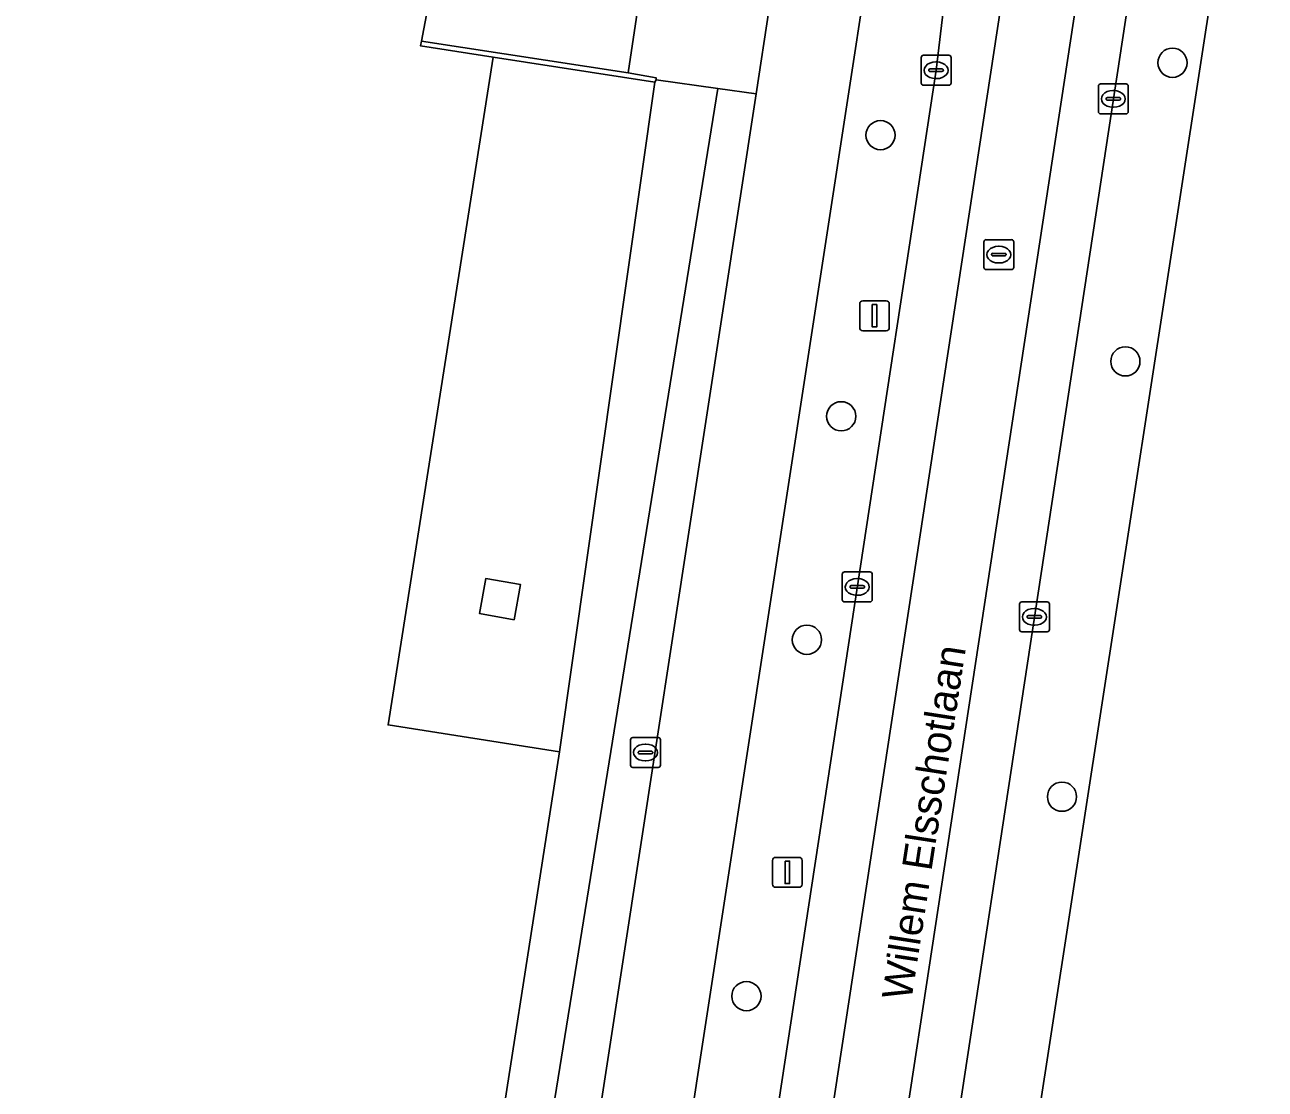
# Model space of a CAD drawing. Extents: x 161090 to 161692, y 379509 to 380907.
# Drawn here: x 161334.14 to 161375.66, y 380617.09 to 380652.7 of the extents above; entities that cross this region are included whole.
import ezdxf

# ---------------------------------------------------------------- set-up
doc = ezdxf.new("R2010")
doc.units = 0
for name, color, linetype in [('IMGEO_Boom', 7, 'Continuous'), ('IMGEO_Brandkraan', 7, 'Continuous'), ('IMGEO_Fietspad_gesloten', 7, 'Continuous'), ('IMGEO_Groenvoorziening', 7, 'Continuous'), ('IMGEO_Haag', 7, 'Continuous'), ('IMGEO_Hek', 7, 'Continuous'), ('IMGEO_Kolk', 7, 'Continuous'), ('IMGEO_Lichtmast', 7, 'Continuous'), ('IMGEO_Muur', 7, 'Continuous'), ('IMGEO_Openbare_ruimte_label', 7, 'Continuous'), ('IMGEO_Pand', 7, 'Continuous'), ('IMGEO_Rijbaan_lokaal_gesloten', 7, 'Continuous'), ('IMGEO_Rijbaan_lokaal_open', 7, 'Continuous'), ('IMGEO_Rioolput', 7, 'Continuous'), ('IMGEO_Terreindeel_gesloten', 7, 'Continuous'), ('IMGEO_Voetpad_open', 7, 'Continuous')]:
    doc.layers.add(name, color=color, linetype=linetype)

msp = doc.modelspace()

# ---------------------------------------------------------------- linework, layer by layer
at = {"layer": 'IMGEO_Boom'}
for centre in [(161372.554, 380651.434), (161362.782, 380649.011), (161370.978, 380641.442), (161361.467, 380639.604), (161360.319, 380632.127), (161368.856, 380626.877), (161358.295, 380620.204)]:
    msp.add_circle(centre, 0.489, dxfattribs=at)
at = {"layer": 'IMGEO_Brandkraan'}
for p, q in [((161354.415, 380627.93), (161354.415, 380628.782)), ((161354.49, 380628.856), (161355.342, 380628.856)), ((161355.416, 380628.782), (161355.416, 380627.93)), ((161354.674, 380628.35), (161354.674, 380628.362)), ((161355.112, 380628.313), (161354.714, 380628.313)), ((161354.717, 380628.399), (161355.115, 380628.399)), ((161354.903, 380628.636), (161354.928, 380628.636)), ((161355.158, 380628.362), (161355.158, 380628.35)), ((161355.342, 380627.856), (161354.49, 380627.856)), ((161354.926, 380628.076), (161354.901, 380628.076))]:
    msp.add_line(p, q, dxfattribs=at)
for points in [[(161354.415, 380627.93), (161354.415, 380628.782)], [(161354.49, 380628.856), (161355.342, 380628.856)], [(161355.416, 380628.782), (161355.416, 380627.93)], [(161355.342, 380627.856), (161354.49, 380627.856)]]:
    msp.add_lwpolyline(points, dxfattribs=at)
for centre, radius, start, end in [((161354.492, 380628.78), 0.0765, 91.552, 178.448), ((161354.492, 380628.78), 0.0765, 91.552, 178.448), ((161355.34, 380628.78), 0.0765, 1.552, 88.448), ((161355.34, 380628.78), 0.0765, 1.552, 88.448), ((161354.714, 380628.359), 0.0403, 85.8775, 175.7526), ((161354.711, 380628.349), 0.0366, 178.938, 274.7102), ((161355.115, 380628.356), 0.043, 264.8664, 352.4533), ((161355.119, 380628.361), 0.0386, 1.7309, 96.639), ((161354.492, 380627.932), 0.0765, 181.552, 268.448), ((161354.492, 380627.932), 0.0765, 181.552, 268.448), ((161355.34, 380627.932), 0.0765, 271.552, 358.448), ((161355.34, 380627.932), 0.0765, 271.552, 358.448)]:
    msp.add_arc(centre, radius, start, end, dxfattribs=at)
for centre, major_axis, ratio, start_param, end_param in [((161354.902, 380628.356), (-0.387, 0.002), 0.722429, 4.712389, 7.853982), ((161354.927, 380628.356), (-0.39, 0.002), 0.717154, 1.570796, 4.712389)]:
    msp.add_ellipse(centre, major_axis=major_axis, ratio=ratio, start_param=start_param, end_param=end_param, dxfattribs=at)
at = {"layer": 'IMGEO_Fietspad_gesloten'}
for points in [[(161365.033, 380672.035), (161366.062, 380679.022), (161370.741, 380709.1), (161371.715, 380716.23), (161380.846, 380774.64), (161377.763, 380775.191), (161374.457, 380753.641), (161374.222, 380752.111), (161368.715, 380716.224), (161367.825, 380710.422), (161362.964, 380678.743), (161362.07, 380672.915), (161359.052, 380653.248), (161358.615, 380650.395), (161352.499, 380610.536), (161352.063, 380607.696), (161344.427, 380557.933), (161343.697, 380553.172), (161343.539, 380552.144), (161341.187, 380536.812), (161341.053, 380535.941), (161340.209, 380530.441), (161339.339, 380524.771), (161336.97, 380509.331)], [(161335.342, 380478.178), (161335.568, 380479.642), (161342.437, 380524.075), (161343.313, 380530.047), (161346.723, 380552.271), (161347.54, 380558.203), (161365.033, 380672.035)]]:
    msp.add_lwpolyline(points, dxfattribs=at)
at = {"layer": 'IMGEO_Groenvoorziening'}
for points in [[(161405.29, 380858.44), (161406.537, 380866.558), (161406.318, 380866.529), (161406.225, 380866.182), (161404.5, 380859.729), (161400.962, 380846.207), (161400.622, 380844.851), (161395.87, 380814.342), (161392.957, 380796.042), (161379.164, 380706.261), (161373.065, 380666.559), (161354.682, 380545.949), (161344.875, 380482.113), (161345.249, 380482.081)], [(161347.003, 380477.776), (161347.606, 380481.216), (161353.592, 380520.726), (161366.925, 380608.735), (161376.121, 380668.459), (161405.29, 380858.44)], [(161483.889, 380845.433), (161405.29, 380858.44), (161376.121, 380668.459), (161366.925, 380608.735), (161353.592, 380520.726), (161347.606, 380481.216)], [(161365.033, 380672.035), (161347.54, 380558.203)], [(161351.073, 380562.281), (161364.643, 380651.182), (161364.91, 380653.432), (161367.178, 380667.879)]]:
    msp.add_lwpolyline(points, dxfattribs=at)
for points in [[(161355.234, 380650.781), (161349.821, 380651.619), (161346.301, 380629.278), (161352.038, 380628.383)], [(161357.34, 380650.575), (161355.268, 380650.867), (161355.234, 380650.781), (161352.038, 380628.383), (161349.332, 380611.003), (161350.91, 380610.77)], [(161358.615, 380650.395), (161357.34, 380650.575), (161350.91, 380610.77), (161352.499, 380610.536)], [(161350.731, 380633.977), (161350.52, 380632.797), (161349.358, 380633.011), (161349.569, 380634.173)]]:
    msp.add_lwpolyline(points, close=True, dxfattribs=at)
at = {"layer": 'IMGEO_Haag'}
msp.add_lwpolyline([(161357.34, 380650.575), (161355.268, 380650.867), (161355.234, 380650.781), (161352.038, 380628.383), (161349.332, 380611.003), (161350.91, 380610.77)], close=True, dxfattribs=at)
at = {"layer": 'IMGEO_Hek'}
msp.add_lwpolyline([(161353.592, 380520.726), (161366.925, 380608.735), (161376.121, 380668.459)], dxfattribs=at)
at = {"layer": 'IMGEO_Kolk'}
for p, q in [((161364.142, 380650.756), (161364.142, 380651.608)), ((161364.217, 380651.682), (161365.069, 380651.682)), ((161365.143, 380651.608), (161365.143, 380650.756)), ((161364.401, 380651.176), (161364.401, 380651.188)), ((161364.839, 380651.139), (161364.441, 380651.139)), ((161364.444, 380651.225), (161364.842, 380651.225)), ((161364.63, 380651.462), (161364.655, 380651.462)), ((161364.885, 380651.188), (161364.885, 380651.176)), ((161365.069, 380650.682), (161364.217, 380650.682)), ((161364.653, 380650.902), (161364.628, 380650.902)), ((161370.149, 380650.724), (161371.001, 380650.724)), ((161370.074, 380649.798), (161370.074, 380650.65)), ((161370.376, 380650.267), (161370.774, 380650.267)), ((161370.562, 380650.504), (161370.587, 380650.504)), ((161371.075, 380650.65), (161371.075, 380649.798)), ((161370.333, 380650.218), (161370.333, 380650.23)), ((161370.771, 380650.181), (161370.373, 380650.181)), ((161370.585, 380649.944), (161370.56, 380649.944)), ((161370.817, 380650.23), (161370.817, 380650.218)), ((161371.001, 380649.724), (161370.149, 380649.724)), ((161361.503, 380633.469), (161361.503, 380634.321)), ((161361.578, 380634.395), (161362.43, 380634.395)), ((161361.991, 380634.175), (161362.016, 380634.175)), ((161362.504, 380634.321), (161362.504, 380633.469)), ((161361.762, 380633.889), (161361.762, 380633.901)), ((161362.2, 380633.852), (161361.802, 380633.852)), ((161361.805, 380633.938), (161362.203, 380633.938)), ((161362.246, 380633.901), (161362.246, 380633.889)), ((161362.43, 380633.395), (161361.578, 380633.395)), ((161362.014, 380633.615), (161361.989, 380633.615)), ((161367.433, 380632.467), (161367.433, 380633.319)), ((161367.508, 380633.393), (161368.36, 380633.393)), ((161368.434, 380633.319), (161368.434, 380632.467)), ((161367.692, 380632.887), (161367.692, 380632.899)), ((161368.13, 380632.85), (161367.732, 380632.85)), ((161367.735, 380632.936), (161368.133, 380632.936)), ((161367.921, 380633.173), (161367.946, 380633.173)), ((161368.176, 380632.899), (161368.176, 380632.887)), ((161367.944, 380632.613), (161367.919, 380632.613)), ((161368.36, 380632.393), (161367.508, 380632.393))]:
    msp.add_line(p, q, dxfattribs=at)
for points in [[(161364.142, 380650.756), (161364.142, 380651.608)], [(161364.217, 380651.682), (161365.069, 380651.682)], [(161365.143, 380651.608), (161365.143, 380650.756)], [(161365.069, 380650.682), (161364.217, 380650.682)], [(161370.149, 380650.724), (161371.001, 380650.724)], [(161370.074, 380649.798), (161370.074, 380650.65)], [(161371.075, 380650.65), (161371.075, 380649.798)], [(161371.001, 380649.724), (161370.149, 380649.724)], [(161361.503, 380633.469), (161361.503, 380634.321)], [(161361.578, 380634.395), (161362.43, 380634.395)], [(161362.504, 380634.321), (161362.504, 380633.469)], [(161362.43, 380633.395), (161361.578, 380633.395)], [(161367.433, 380632.467), (161367.433, 380633.319)], [(161367.508, 380633.393), (161368.36, 380633.393)], [(161368.434, 380633.319), (161368.434, 380632.467)], [(161368.36, 380632.393), (161367.508, 380632.393)]]:
    msp.add_lwpolyline(points, dxfattribs=at)
for centre, radius, start, end in [((161364.219, 380651.606), 0.0765, 91.552, 178.448), ((161364.219, 380651.606), 0.0765, 91.552, 178.448), ((161365.067, 380651.606), 0.0765, 1.552, 88.448), ((161365.067, 380651.606), 0.0765, 1.552, 88.448), ((161364.441, 380651.185), 0.0403, 85.8775, 175.7526), ((161364.438, 380651.175), 0.0366, 178.938, 274.7102), ((161364.842, 380651.182), 0.043, 264.8664, 352.4533), ((161364.846, 380651.187), 0.0386, 1.7309, 96.639), ((161364.219, 380650.758), 0.0765, 181.552, 268.448), ((161364.219, 380650.758), 0.0765, 181.552, 268.448), ((161365.067, 380650.758), 0.0765, 271.552, 358.448), ((161365.067, 380650.758), 0.0765, 271.552, 358.448), ((161370.151, 380650.648), 0.0765, 91.552, 178.448), ((161370.151, 380650.648), 0.0765, 91.552, 178.448), ((161370.999, 380650.648), 0.0765, 1.552, 88.448), ((161370.999, 380650.648), 0.0765, 1.552, 88.448), ((161370.373, 380650.227), 0.0403, 85.8775, 175.7526), ((161370.778, 380650.229), 0.0386, 1.7309, 96.639), ((161370.37, 380650.217), 0.0366, 178.938, 274.7102), ((161370.774, 380650.224), 0.043, 264.8664, 352.4533), ((161370.151, 380649.8), 0.0765, 181.552, 268.448), ((161370.151, 380649.8), 0.0765, 181.552, 268.448), ((161370.999, 380649.8), 0.0765, 271.552, 358.448), ((161370.999, 380649.8), 0.0765, 271.552, 358.448), ((161361.58, 380634.319), 0.0765, 91.552, 178.448), ((161361.58, 380634.319), 0.0765, 91.552, 178.448), ((161362.428, 380634.319), 0.0765, 1.552, 88.448), ((161362.428, 380634.319), 0.0765, 1.552, 88.448), ((161361.802, 380633.898), 0.0403, 85.8775, 175.7526), ((161361.799, 380633.888), 0.0366, 178.938, 274.7102), ((161362.203, 380633.895), 0.043, 264.8664, 352.4533), ((161362.207, 380633.9), 0.0386, 1.7309, 96.639), ((161361.58, 380633.471), 0.0765, 181.552, 268.448), ((161361.58, 380633.471), 0.0765, 181.552, 268.448), ((161362.428, 380633.471), 0.0765, 271.552, 358.448), ((161362.428, 380633.471), 0.0765, 271.552, 358.448), ((161367.51, 380633.317), 0.0765, 91.552, 178.448), ((161367.51, 380633.317), 0.0765, 91.552, 178.448), ((161368.358, 380633.317), 0.0765, 1.552, 88.448), ((161368.358, 380633.317), 0.0765, 1.552, 88.448), ((161367.732, 380632.896), 0.0403, 85.8775, 175.7526), ((161367.729, 380632.886), 0.0366, 178.938, 274.7102), ((161368.133, 380632.893), 0.043, 264.8664, 352.4533), ((161368.137, 380632.898), 0.0386, 1.7309, 96.639), ((161367.51, 380632.469), 0.0765, 181.552, 268.448), ((161367.51, 380632.469), 0.0765, 181.552, 268.448), ((161368.358, 380632.469), 0.0765, 271.552, 358.448), ((161368.358, 380632.469), 0.0765, 271.552, 358.448)]:
    msp.add_arc(centre, radius, start, end, dxfattribs=at)
for centre, major_axis, ratio, start_param, end_param in [((161364.629, 380651.182), (-0.387, 0.002), 0.722429, 4.712389, 7.853982), ((161364.654, 380651.182), (-0.39, 0.002), 0.717154, 1.570796, 4.712389), ((161370.561, 380650.224), (-0.387, 0.002), 0.722429, 4.712389, 7.853982), ((161370.586, 380650.224), (-0.39, 0.002), 0.717154, 1.570796, 4.712389), ((161361.99, 380633.895), (-0.387, 0.002), 0.722429, 4.712389, 7.853982), ((161362.015, 380633.895), (-0.39, 0.002), 0.717154, 1.570796, 4.712389), ((161367.92, 380632.893), (-0.387, 0.002), 0.722429, 4.712389, 7.853982), ((161367.945, 380632.893), (-0.39, 0.002), 0.717154, 1.570796, 4.712389)]:
    msp.add_ellipse(centre, major_axis=major_axis, ratio=ratio, start_param=start_param, end_param=end_param, dxfattribs=at)
at = {"layer": 'IMGEO_Lichtmast'}
for p, q in [((161362.086, 380642.569), (161362.086, 380643.369)), ((161362.086, 380643.369), (161362.086, 380642.569)), ((161362.186, 380643.469), (161362.976, 380643.469)), ((161362.976, 380643.469), (161362.186, 380643.469)), ((161363.076, 380643.369), (161363.076, 380642.569)), ((161363.076, 380642.569), (161363.076, 380643.369)), ((161362.976, 380642.469), (161362.186, 380642.469)), ((161362.186, 380642.469), (161362.976, 380642.469)), ((161359.17, 380623.945), (161359.17, 380624.745)), ((161359.17, 380624.745), (161359.17, 380623.945)), ((161359.27, 380624.845), (161360.06, 380624.845)), ((161360.06, 380624.845), (161359.27, 380624.845)), ((161360.16, 380624.745), (161360.16, 380623.945)), ((161360.16, 380623.945), (161360.16, 380624.745)), ((161360.06, 380623.845), (161359.27, 380623.845)), ((161359.27, 380623.845), (161360.06, 380623.845))]:
    msp.add_line(p, q, dxfattribs=at)
for points in [[(161362.506, 380643.344), (161362.656, 380643.344), (161362.656, 380642.594), (161362.506, 380642.594), (161362.506, 380643.344)], [(161359.59, 380624.72), (161359.74, 380624.72), (161359.74, 380623.97), (161359.59, 380623.97), (161359.59, 380624.72)]]:
    msp.add_lwpolyline(points, dxfattribs=at)
for centre, start, end in [((161362.186, 380643.369), 90, 180), ((161362.186, 380643.369), 90, 180), ((161362.976, 380643.369), 0, 90), ((161362.976, 380643.369), 360, 90), ((161362.186, 380642.569), 180, 270), ((161362.186, 380642.569), 180, 270), ((161362.976, 380642.569), 270, 0), ((161362.976, 380642.569), 270, 0), ((161359.27, 380624.745), 90, 180), ((161359.27, 380624.745), 90, 180), ((161360.06, 380624.745), 0, 90), ((161360.06, 380624.745), 360, 90), ((161359.27, 380623.945), 180, 270), ((161359.27, 380623.945), 180, 270), ((161360.06, 380623.945), 270, 0), ((161360.06, 380623.945), 270, 0)]:
    msp.add_arc(centre, 0.1, start, end, dxfattribs=at)
at = {"layer": 'IMGEO_Muur'}
msp.add_lwpolyline([(161355.234, 380650.781), (161355.268, 380650.867), (161355.271, 380650.933), (161354.34, 380651.099), (161347.42, 380652.158), (161347.389, 380651.995), (161349.821, 380651.619)], close=True, dxfattribs=at)
at = {"layer": 'IMGEO_Pand'}
msp.add_lwpolyline([(161349.332, 380611.003), (161352.038, 380628.383), (161346.301, 380629.278), (161349.821, 380651.619), (161347.389, 380651.995), (161347.42, 380652.158), (161347.94, 380654.933), (161347.981, 380655.15), (161350.309, 380654.767), (161351.908, 380665.091), (161349.549, 380665.469), (161350.974, 380674.355), (161351.021, 380674.65), (161350.918, 380674.666), (161328.544, 380678.189), (161323.902, 380678.927), (161318.782, 380679.713), (161325.548, 380722.987)], dxfattribs=at)
at = {"layer": 'IMGEO_Rijbaan_lokaal_gesloten'}
for points in [[(161375.194, 380708.235), (161388.922, 380797.51), (161396.234, 380843.996), (161396.663, 380846.991), (161394.901, 380847.24), (161394.664, 380845.21), (161392.523, 380831.905), (161390.03, 380815.808), (161385.145, 380784.362), (161382.973, 380770.386), (161375.271, 380720.147), (161372.778, 380704.125), (161369.527, 380682.914), (161367.178, 380667.879), (161364.91, 380653.432), (161364.643, 380651.182), (161351.073, 380562.281), (161348.823, 380547.566), (161346.783, 380533.972), (161344.46, 380518.897), (161338.966, 380482.69)], [(161344.822, 380481.77), (161344.875, 380482.113), (161354.682, 380545.949), (161373.065, 380666.559), (161379.164, 380706.261), (161392.957, 380796.042), (161395.87, 380814.342), (161400.622, 380844.851), (161400.962, 380846.207), (161399.153, 380846.596), (161398.722, 380843.492), (161391.386, 380797.079), (161377.702, 380708.239), (161342.463, 380477.394), (161346.509, 380476.771)], [(161335.342, 380478.178), (161339.984, 380477.773), (161375.194, 380708.235)]]:
    msp.add_lwpolyline(points, dxfattribs=at)
at = {"layer": 'IMGEO_Rijbaan_lokaal_open'}
msp.add_lwpolyline([(161388.922, 380797.51), (161375.194, 380708.235), (161339.984, 380477.773), (161342.463, 380477.394), (161377.702, 380708.239), (161391.386, 380797.079), (161398.722, 380843.492), (161399.153, 380846.596), (161398.722, 380846.664), (161396.663, 380846.991), (161396.234, 380843.996)], close=True, dxfattribs=at)
at = {"layer": 'IMGEO_Rioolput'}
for p, q in [((161366.243, 380644.588), (161366.243, 380645.44)), ((161366.318, 380645.514), (161367.17, 380645.514)), ((161366.731, 380645.294), (161366.756, 380645.294)), ((161367.244, 380645.44), (161367.244, 380644.588)), ((161366.502, 380645.008), (161366.502, 380645.02)), ((161366.94, 380644.971), (161366.542, 380644.971)), ((161366.545, 380645.057), (161366.943, 380645.057)), ((161366.986, 380645.02), (161366.986, 380645.008)), ((161367.17, 380644.514), (161366.318, 380644.514)), ((161366.754, 380644.734), (161366.729, 380644.734))]:
    msp.add_line(p, q, dxfattribs=at)
for points in [[(161366.243, 380644.588), (161366.243, 380645.44)], [(161366.318, 380645.514), (161367.17, 380645.514)], [(161367.244, 380645.44), (161367.244, 380644.588)], [(161367.17, 380644.514), (161366.318, 380644.514)]]:
    msp.add_lwpolyline(points, dxfattribs=at)
for centre, radius, start, end in [((161366.32, 380645.438), 0.0765, 91.552, 178.448), ((161366.32, 380645.438), 0.0765, 91.552, 178.448), ((161367.168, 380645.438), 0.0765, 1.552, 88.448), ((161367.168, 380645.438), 0.0765, 1.552, 88.448), ((161366.542, 380645.017), 0.0403, 85.8775, 175.7526), ((161366.539, 380645.007), 0.0366, 178.938, 274.7102), ((161366.943, 380645.014), 0.043, 264.8664, 352.4533), ((161366.947, 380645.019), 0.0386, 1.7309, 96.639), ((161366.32, 380644.59), 0.0765, 181.552, 268.448), ((161366.32, 380644.59), 0.0765, 181.552, 268.448), ((161367.168, 380644.59), 0.0765, 271.552, 358.448), ((161367.168, 380644.59), 0.0765, 271.552, 358.448)]:
    msp.add_arc(centre, radius, start, end, dxfattribs=at)
for centre, major_axis, ratio, start_param, end_param in [((161366.73, 380645.014), (-0.387, 0.002), 0.722429, 4.712389, 7.853982), ((161366.755, 380645.014), (-0.39, 0.002), 0.717154, 1.570796, 4.712389)]:
    msp.add_ellipse(centre, major_axis=major_axis, ratio=ratio, start_param=start_param, end_param=end_param, dxfattribs=at)
at = {"layer": 'IMGEO_Terreindeel_gesloten'}
msp.add_lwpolyline([(161350.52, 380632.797), (161350.731, 380633.977), (161349.569, 380634.173), (161349.358, 380633.011)], close=True, dxfattribs=at)
at = {"layer": 'IMGEO_Voetpad_open'}
for points in [[(161354.752, 380653.867), (161347.94, 380654.933), (161347.42, 380652.158), (161354.34, 380651.099)], [(161359.052, 380653.248), (161357.919, 380653.408), (161355.744, 380653.715), (161354.752, 380653.867), (161354.34, 380651.099), (161355.271, 380650.933), (161355.268, 380650.867), (161357.34, 380650.575), (161358.615, 380650.395)]]:
    msp.add_lwpolyline(points, close=True, dxfattribs=at)

# ---------------------------------------------------------------- texts
at = {"layer": 'IMGEO_Openbare_ruimte_label'}
msp.add_text('Willem Elsschotlaan', height=1, rotation=81.1972, dxfattribs=at).set_placement((161363.812, 380620.031))

doc.saveas('drawing.dxf')
